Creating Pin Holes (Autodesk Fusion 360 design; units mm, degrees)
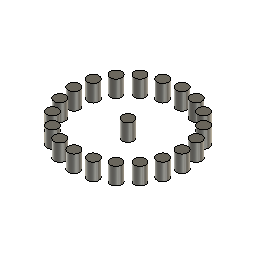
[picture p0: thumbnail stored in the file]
parameter "Diameter" = 10
parameter "Higth" = 15
parameter "Ss" = 15 (= "Diameter * 1.5")
parameter "Circumcircle_R" = 47.9434 (= "Ss / ( 2 * sin(( 180 / n ) * 1 deg) )")
sketch "Sketch1" plane through (0, 0, 0) normal (0, 0, 1) x axis (1, 0, 0)
  circle C1 centre (0, 47.9434) radius 5
  point P1 (0, 0)
  point P2 (0, 47.9434)
  vertical P1 P2
  dimension "d7" diameter C1 = 10 (= "Diameter")
  dimension "d12" distance P1 P2 = 47.9434 (= "Circumcircle_R")
extrude "Extrude1" new body sketch "Sketch1" along normal blind 15 (= "Higth")
circular_pattern "C-Pattern1" TotalAngle 360
sketch "Sketch2" plane through (0, 0, 0) normal (0, 0, 1) x axis (1, 0, 0)
  circle C1 centre (0, 0) radius 5
  point P1 (0, 0)
  point P2 (0, 0)
  coincident P1 P2
  dimension "d13" diameter C1 = 10 (= "Diameter")
extrude "Extrude2" new body sketch "Sketch2" along normal blind 15 (= "Higth")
